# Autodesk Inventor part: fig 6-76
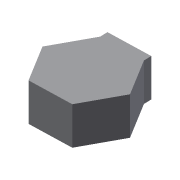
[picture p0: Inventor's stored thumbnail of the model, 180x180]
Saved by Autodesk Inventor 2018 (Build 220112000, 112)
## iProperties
Created: 2009-03
Part Number: fig 6-76
Document SubType Name: Modeling
Designer: Sham
Density: 1 g/cm^3
Material: Generic
Appearance: Default
Author: Sham
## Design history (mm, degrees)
sketch "Sketch5"
  geometry: L1 (-5.929, 9.627)-(5.372, 9.948); L2 (5.372, 9.948)-(11.301, 0.321); L3 (11.301, 0.321)-(5.929, -9.627); L4 (5.929, -9.627)-(-5.372, -9.948); L5 (-5.372, -9.948)-(-11.301, -0.321); L6 (-11.301, -0.321)-(-5.929, 9.627); 1 further point
  constraints: 12 end point, 13 other
extrude "Extrusion3" new body sketch "Sketch5" distance "d13" = 10; taper "d14" = 0 deg
thicken "Thicken2" dims "d15" = 2, "d16" = 2
body "Solid4"
